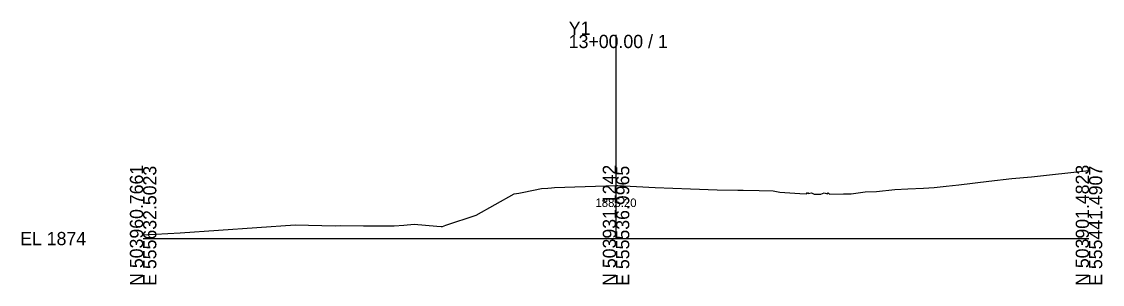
# Model space of a CAD drawing. Extents: x -26 to 1503, y -10 to 5015.
# Drawn here: x -25.7 to 202.8, y 2990.3 to 3045.9 of the extents above; entities that cross this region are included whole.
import ezdxf

# ---------------------------------------------------------------- set-up
doc = ezdxf.new("R2010")
doc.units = 0
for name, color, linetype in [('Default', 7, 'Continuous'), ('Exist Cross Section Cell', 7, 'Continuous'), ('Exist XS Center Line Elevation Label', 7, 'Continuous'), ('Exist XS Ground Line', 7, 'Continuous')]:
    doc.layers.add(name, color=color, linetype=linetype)

msp = doc.modelspace()

# ---------------------------------------------------------------- linework, layer by layer
at = {"layer": 'Exist Cross Section Cell'}
for p, q in [((100, 3000), (100, 3043.1)), ((0, 3000), (100, 3000)), ((100, 3000), (200, 3000))]:
    msp.add_line(p, q, dxfattribs=at)
at = {"layer": 'Exist XS Ground Line'}
for p, q in [((187.84, 3013.09), (200, 3014.37)), ((172.51, 3011.38), (178.83, 3012.11)), ((178.83, 3012.11), (183.72, 3012.68)), ((183.72, 3012.68), (187.84, 3013.09)), ((79.47, 3009.61), (80.47, 3009.8)), ((80.47, 3009.8), (84.23, 3010.58)), ((84.23, 3010.58), (85.57, 3010.68)), ((85.57, 3010.68), (86.38, 3010.75)), ((86.38, 3010.75), (86.96, 3010.79)), ((86.96, 3010.79), (93.44, 3011.01)), ((93.44, 3011.01), (100, 3011.2)), ((100, 3011.2), (100.39, 3011.21)), ((100.39, 3011.21), (108.29, 3010.82)), ((108.29, 3010.82), (115.76, 3010.53)), ((115.76, 3010.53), (121.4, 3010.3)), ((121.4, 3010.3), (125.75, 3010.23)), ((125.75, 3010.23), (126.89, 3010.21)), ((126.89, 3010.21), (130.27, 3010.19)), ((130.27, 3010.19), (133.25, 3010.09)), ((133.25, 3010.09), (134.63, 3009.84)), ((134.63, 3009.84), (138.83, 3009.57)), ((149.72, 3009.45), (152.71, 3009.9)), ((152.71, 3009.9), (155.08, 3009.97)), ((155.08, 3009.97), (158.97, 3010.4)), ((158.97, 3010.4), (161.73, 3010.5)), ((161.73, 3010.5), (165.03, 3010.68)), ((165.03, 3010.68), (167.27, 3010.83)), ((167.27, 3010.83), (169.83, 3011.09)), ((169.83, 3011.09), (172.51, 3011.38)), ((70.42, 3004.93), (78.49, 3009.45)), ((78.49, 3009.45), (79.47, 3009.61)), ((138.83, 3009.57), (140.3, 3009.49)), ((140.3, 3009.49), (140.52, 3009.74)), ((140.52, 3009.74), (140.65, 3009.56)), ((140.65, 3009.56), (141.34, 3009.69)), ((141.34, 3009.69), (141.89, 3009.36)), ((141.89, 3009.36), (143.27, 3009.36)), ((143.27, 3009.36), (144.03, 3009.65)), ((144.03, 3009.65), (144.69, 3009.5)), ((144.69, 3009.5), (144.85, 3009.71)), ((144.85, 3009.71), (145.15, 3009.42)), ((145.15, 3009.42), (148.11, 3009.43)), ((148.11, 3009.43), (149.72, 3009.45)), ((55.11, 3002.84), (57.31, 3003.04)), ((57.31, 3003.04), (62.13, 3002.65)), ((64.01, 3002.86), (70.42, 3004.93)), ((0, 3000.78), (7.86, 3001.23)), ((7.86, 3001.23), (32.13, 3002.9)), ((32.13, 3002.9), (40.61, 3002.7)), ((40.61, 3002.7), (41.75, 3002.74)), ((41.75, 3002.74), (46.63, 3002.69)), ((46.63, 3002.69), (53.08, 3002.7)), ((53.08, 3002.7), (55.11, 3002.84)), ((62.13, 3002.65), (62.99, 3002.57)), ((62.99, 3002.57), (63.3, 3002.55)), ((63.3, 3002.55), (64.01, 3002.86))]:
    msp.add_line(p, q, dxfattribs=at)

# ---------------------------------------------------------------- texts
at = {"layer": 'Default'}
msp.add_text('-', height=0.0001, dxfattribs=at).set_placement((0, 3000))
at = {"layer": 'Exist Cross Section Cell'}
for s, p in [('Y1', (90, 3043.1)), ('13+00.00 / 1', (90, 3040.3)), ('EL 1874', (-26, 2998.6))]:
    msp.add_text(s, height=2.8, dxfattribs=at).set_placement(p)
for s, p in [('N 503960.7661', (0, 2990)), ('E 555632.5023', (2.8, 2990)), ('N 503931.1242', (100, 2990)), ('E 555536.9965', (102.8, 2990)), ('N 503901.4823', (200, 2990)), ('E 555441.4907', (202.8, 2990))]:
    msp.add_text(s, height=2.8, rotation=90, dxfattribs=at).set_placement(p)
at = {"layer": 'Exist XS Center Line Elevation Label'}
msp.add_text('1885.20', height=1.8, dxfattribs=at).set_placement((95.64, 3006.68))

doc.saveas('drawing.dxf')
